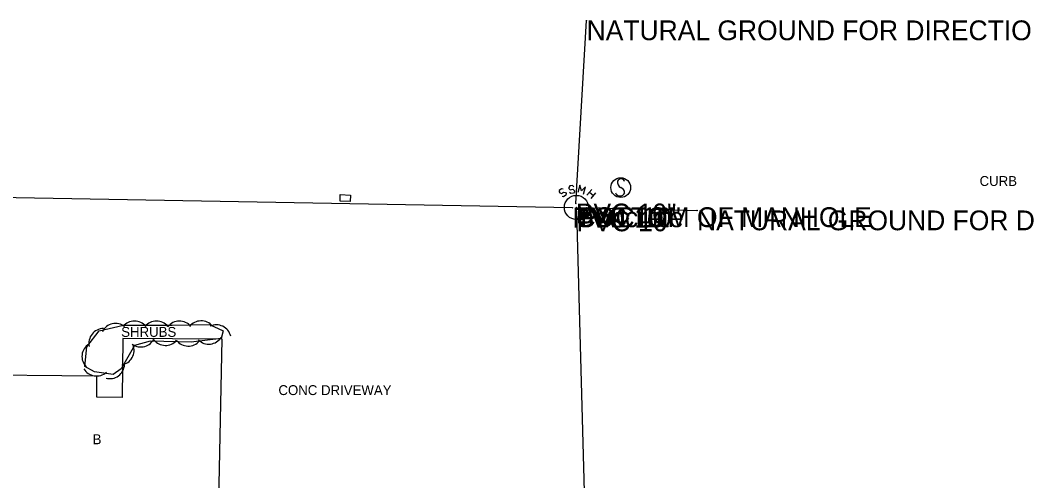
# Model space of a CAD drawing. Extents: x 1802180 to 1804859, y 572524 to 575172.
# Drawn here: x 1804301.3 to 1804555.9, y 574014.2 to 574130.7 of the extents above; entities that cross this region are included whole.
import ezdxf

# ---------------------------------------------------------------- set-up
doc = ezdxf.new("R2010")
doc.units = 0
for name, color, linetype in [('S_BUILDING', 7, 'Continuous'), ('S_BUILDING_ANNOT', 7, 'Continuous'), ('S_CURB_ANNOT', 7, 'Continuous'), ('S_DRIVEWAY_ANNOT', 7, 'Continuous'), ('S_MANHOLE_ANNOT', 7, 'Continuous'), ('S_MISC_STRUCTURES', 7, 'Continuous'), ('S_SANITARY_SEWER', 7, 'Continuous'), ('S_SANITARY_SEWER_ANNOT', 7, 'Continuous'), ('S_SIGN', 7, 'Continuous'), ('S_TREE', 7, 'Continuous'), ('S_TREE_ANNOT', 7, 'Continuous'), ('S_UTL_PT_SYM', 7, 'Continuous')]:
    doc.layers.add(name, color=color, linetype=linetype)

msp = doc.modelspace()

# ---------------------------------------------------------------- linework, layer by layer
at = {"layer": 'S_BUILDING'}
msp.add_lwpolyline([(1804284.8, 574002.25), (1804351.35, 574001.03), (1804352.38, 574050.04), (1804327.23, 574050.19), (1804327.07, 574035.27), (1804320.62, 574035.36), (1804320.63, 574040.65), (1804285.24, 574041.03), (1804284.8, 574002.25)], dxfattribs=at)
at = {"layer": 'S_MISC_STRUCTURES'}
msp.add_lwpolyline([(1804382.16, 574086.59), (1804384.77, 574086.47), (1804384.69, 574084.84), (1804382.2, 574084.96), (1804382.16, 574086.59)], dxfattribs=at)
at = {"layer": 'S_SANITARY_SEWER'}
for p, q in [((1804441.81, 574084.32), (1804444.53, 574130.64)), ((1804440.94, 574083.26), (1803703, 574096.66)), ((1804438.16, 574088.04), (1804437.61, 574087.65)), ((1804438.58, 574087.96), (1804438.16, 574088.04)), ((1804444.59, 574086.41), (1804445.83, 574087.89)), ((1804437.61, 574087.65), (1804437.54, 574087.27)), ((1804437.54, 574087.27), (1804437.73, 574087)), ((1804437.73, 574087), (1804438.16, 574086.88)), ((1804438.16, 574086.88), (1804438.7, 574087.23)), ((1804438.7, 574086.07), (1804438.31, 574086.14)), ((1804438.7, 574087.23), (1804439.16, 574087.15)), ((1804439.24, 574086.45), (1804438.7, 574086.07)), ((1804439.16, 574087.15), (1804439.32, 574086.88)), ((1804439.32, 574086.88), (1804439.24, 574086.45)), ((1804445.25, 574087.19), (1804446.22, 574086.38)), ((1804446.8, 574087.07), (1804445.56, 574085.6)), ((1804442.91, 574083.35), (1804472.45, 574082.58)), ((1804441.94, 574082.32), (1804444.2, 574000.45))]:
    msp.add_line(p, q, dxfattribs=at)
for points in [[(1804441.26, 574088.58), (1804440.91, 574088.86), (1804440.25, 574088.78), (1804440.02, 574088.43), (1804440.05, 574088.12), (1804440.4, 574087.81), (1804441.02, 574087.93), (1804441.41, 574087.62), (1804441.45, 574087.31), (1804441.18, 574086.92), (1804440.56, 574086.84), (1804440.21, 574087.11)], [(1804443.7, 574086.72), (1804444.24, 574088.58), (1804443.19, 574087.58), (1804442.81, 574089.01), (1804442.26, 574087.15)]]:
    msp.add_lwpolyline(points, dxfattribs=at)
msp.add_circle((1804441.94, 574083.35), 3.05, dxfattribs=at)
at = {"layer": 'S_SIGN'}
msp.add_circle((1804453.15, 574088.37), 2.5, dxfattribs=at)
for centre, radius, start, end in [((1804453.22, 574089.64), 0.952, 16.5258, 156.8957), ((1804453.84, 574089.7), 1.51, 167.1196, 241.9813), ((1804452.74, 574087.02), 1.4, 358.6529, 73.7063), ((1804452.99, 574087.54), 1.28, 204.641, 335.359)]:
    msp.add_arc(centre, radius, start, end, dxfattribs=at)
at = {"layer": 'S_TREE'}
msp.add_lwpolyline([(1804317.6, 574043.1), (1804318.15, 574048.13), (1804321.27, 574052.12), (1804327.43, 574053.57), (1804339.67, 574053.58), (1804349.15, 574053.77), (1804352.57, 574052.14), (1804352.1, 574050.17), (1804344.52, 574049.3), (1804334.14, 574049.54), (1804330.18, 574048.45), (1804326.84, 574042.57), (1804324.78, 574041.07), (1804320.09, 574041.8), (1804317.6, 574043.1)], dxfattribs=at)
for centre, start, end in [((1804322.38, 574049), 91.2021, 192.799), ((1804325.43, 574050.3), 52.4579, 154.0548), ((1804330.17, 574050.88), 39.234, 140.831), ((1804335.74, 574050.88), 39.234, 140.831), ((1804341.58, 574050.89), 40.3902, 141.9871), ((1804347.05, 574050.93), 40.3902, 141.9871), ((1804350.91, 574049.92), 13.6905, 115.2874), ((1804331.79, 574051.8), 234.6432, 336.2401), ((1804338, 574052.18), 217.8442, 319.4411), ((1804343.78, 574052.01), 217.8442, 319.4411), ((1804348.95, 574052.51), 225.7827, 327.3796), ((1804320.62, 574045.67), 122.9153, 224.5122), ((1804326.35, 574047.21), 279.5947, 21.1916), ((1804320.58, 574044.45), 210.368, 311.9649), ((1804323.94, 574043.78), 255.1848, 356.7817)]:
    msp.add_arc(centre, 3.73, start, end, dxfattribs=at)
at = {"layer": 'S_UTL_PT_SYM'}
for points in [[(1804444.53, 574130.64), (1804444.53, 574130.69), (1804444.53, 574130.64), (1804444.48, 574130.64), (1804444.53, 574130.64), (1804444.53, 574130.59), (1804444.53, 574130.64), (1804444.58, 574130.64)], [(1804440.94, 574083.26), (1804440.94, 574083.31), (1804440.94, 574083.26), (1804440.89, 574083.26), (1804440.94, 574083.26), (1804440.94, 574083.21), (1804440.94, 574083.26), (1804440.99, 574083.26)], [(1804441.81, 574084.32), (1804441.81, 574084.37), (1804441.81, 574084.32), (1804441.76, 574084.32), (1804441.81, 574084.32), (1804441.81, 574084.27), (1804441.81, 574084.32), (1804441.86, 574084.32)], [(1804441.98, 574083.39), (1804441.98, 574083.44), (1804441.98, 574083.39), (1804441.93, 574083.39), (1804441.98, 574083.39), (1804441.98, 574083.34), (1804441.98, 574083.39), (1804442.03, 574083.39)], [(1804442.91, 574083.35), (1804442.91, 574083.4), (1804442.91, 574083.35), (1804442.86, 574083.35), (1804442.91, 574083.35), (1804442.91, 574083.3), (1804442.91, 574083.35), (1804442.96, 574083.35)], [(1804441.94, 574082.32), (1804441.94, 574082.37), (1804441.94, 574082.32), (1804441.89, 574082.32), (1804441.94, 574082.32), (1804441.94, 574082.27), (1804441.94, 574082.32), (1804441.99, 574082.32)], [(1804472.45, 574082.58), (1804472.45, 574082.63), (1804472.45, 574082.58), (1804472.4, 574082.58), (1804472.45, 574082.58), (1804472.45, 574082.53), (1804472.45, 574082.58), (1804472.5, 574082.58)]]:
    msp.add_lwpolyline(points, dxfattribs=at)

# ---------------------------------------------------------------- texts
at = {"layer": 'S_BUILDING_ANNOT'}
msp.add_text('B', height=2.5, dxfattribs=at).set_placement((1804319.6, 574023.47))
at = {"layer": 'S_CURB_ANNOT'}
msp.add_text('CURB', height=2.5, dxfattribs=at).set_placement((1804543.9, 574088.78))
at = {"layer": 'S_DRIVEWAY_ANNOT'}
msp.add_text('CONC DRIVEWAY', height=2.5, dxfattribs=at).set_placement((1804366.58, 574035.9))
at = {"layer": 'S_MANHOLE_ANNOT'}
msp.add_text('BOTTOM OF MANHOLE', height=5, dxfattribs=at).set_placement((1804441.98, 574078.39))
at = {"layer": 'S_SANITARY_SEWER_ANNOT'}
for s, p in [('NATURAL GROUND FOR DIRECTION ONLY    ', (1804444.53, 574125.64)), ('PVC 10" ', (1804440.94, 574078.26)), ('Concrete', (1804441.94, 574078.35)), ('PVC 10" ', (1804441.81, 574079.32)), ('PVC 10" ', (1804442.91, 574078.35)), ('PVC 10" ', (1804441.94, 574077.32)), ('NATURAL GROUND FOR DIRECTION ONLY    ', (1804472.45, 574077.58))]:
    msp.add_text(s, height=5, dxfattribs=at).set_placement(p)
at = {"layer": 'S_TREE_ANNOT'}
msp.add_text('SHRUBS', height=2.5, dxfattribs=at).set_placement((1804326.82, 574050.62))

doc.saveas('drawing.dxf')
